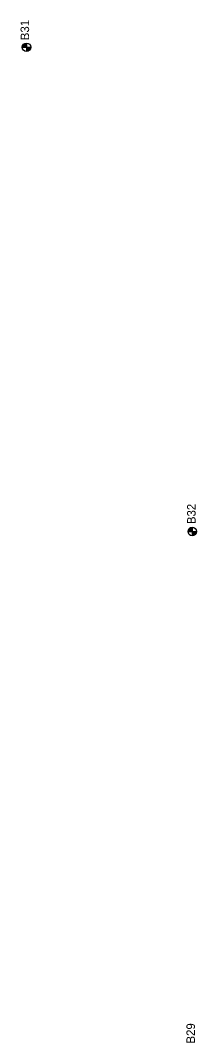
# Model space of a CAD drawing. Extents: x 331323 to 388339, y 121519 to 205315.
# Drawn here: x 361742 to 361949, y 145123 to 146325 of the extents above; entities that cross this region are included whole.
import ezdxf

# ---------------------------------------------------------------- set-up
doc = ezdxf.new("R2010")
doc.units = 0
doc.layers.add('E_SOIL_BORE2 [KAPUR_CADDS_LEVELS]', color=7, linetype='Continuous')
doc.layers.add('P_MARK', color=7, linetype='Continuous')

msp = doc.modelspace()

# ---------------------------------------------------------------- linework, layer by layer
at = {"layer": 'P_MARK'}
for p, q in [((361743.9, 146293.4), (361753.9, 146293.4)), ((361748.9, 146298.4), (361748.9, 146288.4)), ((361943.7, 145729.1), (361943.7, 145719.1)), ((361938.7, 145724.1), (361948.7, 145724.1))]:
    msp.add_line(p, q, dxfattribs=at)
for centre in [(361748.9, 146293.4), (361943.7, 145724.1)]:
    msp.add_circle(centre, 5, dxfattribs=at)
for centre, radius, start, end in [((361748.9, 146293.4), 4.5, 89.9869, 179.9869), ((361748.9, 146293.4), 4, 89.9869, 179.9869), ((361748.9, 146293.4), 3.5, 89.9869, 179.9869), ((361748.9, 146293.4), 3, 89.9869, 179.9869), ((361748.9, 146293.4), 2.5, 89.9869, 179.9869), ((361748.9, 146293.4), 2, 89.9869, 179.9869), ((361748.9, 146293.4), 1.5, 89.9869, 179.9869), ((361748.9, 146293.4), 1, 89.9869, 179.9869), ((361748.9, 146293.4), 0.5, 89.9869, 179.9869), ((361748.9, 146293.4), 4.5, 269.9869, 359.9869), ((361748.9, 146293.4), 4, 269.9869, 359.9869), ((361748.9, 146293.4), 3.5, 269.9869, 359.9869), ((361748.9, 146293.4), 3, 269.9869, 359.9869), ((361748.9, 146293.4), 2.5, 269.9869, 359.9869), ((361748.9, 146293.4), 2, 269.9869, 359.9869), ((361748.9, 146293.4), 1.5, 269.9869, 359.9869), ((361748.9, 146293.4), 1, 269.9869, 359.9869), ((361748.9, 146293.4), 0.5, 269.9869, 359.9869), ((361943.7, 145724.1), 4.5, 89.9869, 179.9869), ((361943.7, 145724.1), 4, 89.9869, 179.9869), ((361943.7, 145724.1), 3.5, 89.9869, 179.9869), ((361943.7, 145724.1), 3, 89.9869, 179.9869), ((361943.7, 145724.1), 2.5, 89.9869, 179.9869), ((361943.7, 145724.1), 2, 89.9869, 179.9869), ((361943.7, 145724.1), 1.5, 89.9869, 179.9869), ((361943.7, 145724.1), 1, 89.9869, 179.9869), ((361943.7, 145724.1), 0.5, 89.9869, 179.9869), ((361943.7, 145724.1), 4.5, 269.9869, 359.9869), ((361943.7, 145724.1), 4, 269.9869, 359.9869), ((361943.7, 145724.1), 3.5, 269.9869, 359.9869), ((361943.7, 145724.1), 3, 269.9869, 359.9869), ((361943.7, 145724.1), 2.5, 269.9869, 359.9869), ((361943.7, 145724.1), 2, 269.9869, 359.9869), ((361943.7, 145724.1), 1.5, 269.9869, 359.9869), ((361943.7, 145724.1), 1, 269.9869, 359.9869), ((361943.7, 145724.1), 0.5, 269.9869, 359.9869)]:
    msp.add_arc(centre, radius, start, end, dxfattribs=at)

# ---------------------------------------------------------------- texts
at = {"layer": 'E_SOIL_BORE2 [KAPUR_CADDS_LEVELS]'}
for s, p in [('B31', (361752, 146301.8)), ('B32', (361947.6, 145732.9)), ('B29', (361946.8, 145122.2))]:
    msp.add_text(s, height=10, rotation=89.9869, dxfattribs=at).set_placement(p)

doc.saveas('drawing.dxf')
